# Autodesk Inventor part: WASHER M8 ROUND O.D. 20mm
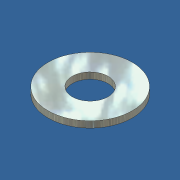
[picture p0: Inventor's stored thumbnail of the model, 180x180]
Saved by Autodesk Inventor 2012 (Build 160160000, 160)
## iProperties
Created: 2007-04
Part Number: WASHER M8 ROUND O.D. 20mm
Material: Steel
Document SubType Name: Modeling
Designer: Andy Moles
Density: 7.85 g/cm^3
Mass: 3.03105 g
Surface Area: 6.49132 cm^2
Volume: 0.386121 cm^3
Author: Andy Moles
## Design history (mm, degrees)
sketch "Sketch1"
  geometry: C1 r 4.25 at (0, 0); C2 r 10 at (0, 0); 1 further point
  constraints: 2 centre point, 2 coincident
  dimensions: "d0" = 8.5 diameter of C1; "d1" = 20 diameter of C2
extrude "Extrusion1" new body sketch "Sketch1" distance "d2" = 1.5; taper "d3" = 0 deg
body "Solid1"
